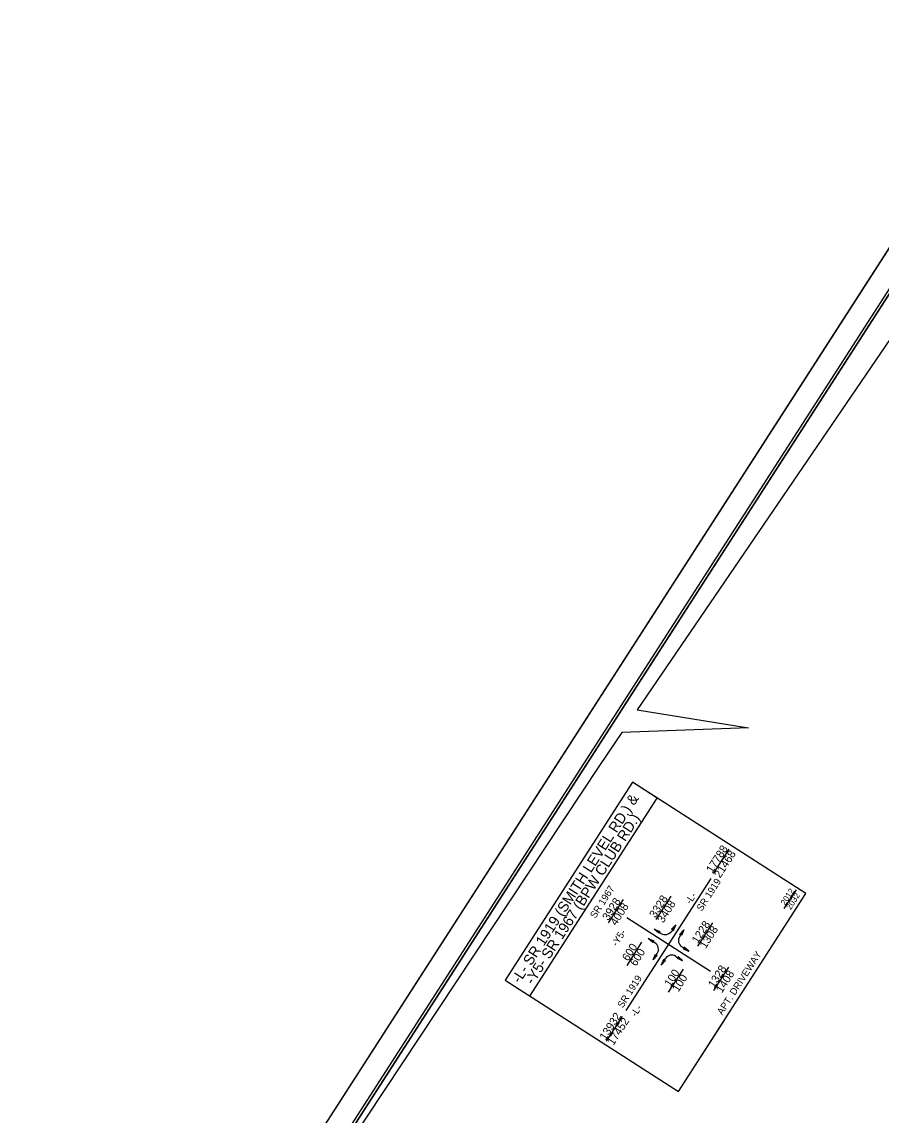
# Model space of a CAD drawing. Extents: x 1976127 to 1977958, y 779377 to 781490.
# Drawn here: x 1976127 to 1976899, y 780410 to 781394 of the extents above; entities that cross this region are included whole.
import ezdxf

# ---------------------------------------------------------------- set-up
doc = ezdxf.new("R2010")
doc.units = 0
for name, color, linetype in [('Prop PHM Label Text', 7, 'Continuous'), ('Prop PHM White Label Box', 7, 'Continuous'), ('Sheet Clip Boundary CELL', 7, 'Continuous'), ('Sheet Cutting Line CELL', 7, 'Continuous'), ('Sheet North Arrow CELL', 7, 'Continuous'), ('Sheet Plan CELL', 7, 'Continuous'), ('Sheet Plan Layout CELL', 7, 'Continuous'), ('Sheet Plot Border Inside CELL', 7, 'Continuous'), ('Sheet Plot Border Outside CELL', 7, 'Continuous')]:
    doc.layers.add(name, color=color, linetype=linetype)

msp = doc.modelspace()

# ---------------------------------------------------------------- linework, layer by layer
at = {"layer": 'Prop PHM Label Text'}
for p, q in [((1976697.94, 780695.58), (1976675.81, 780709.8)), ((1976583.34, 780517.38), (1976697.94, 780695.58)), ((1976748.46, 780627.55), (1976762.65, 780649.61)), ((1976670.04, 780504.29), (1976746.4, 780623.03)), ((1976812.25, 780596.14), (1976823.07, 780612.96)), ((1976654.2, 780583.36), (1976667.6, 780604.18)), ((1976697.01, 780586.39), (1976710.4, 780607.22)), ((1976745.81, 780539.49), (1976670.63, 780587.84)), ((1976714.61, 780581.53), (1976710.97, 780575.87)), ((1976734.43, 780562.33), (1976747.82, 780583.16)), ((1976695.85, 780565.3), (1976689.89, 780569.13)), ((1976701.29, 780573.77), (1976695.34, 780577.6)), ((1976721.82, 780576.89), (1976718.18, 780571.23)), ((1976670.8, 780544.91), (1976684.19, 780565.74)), ((1976720.28, 780561.56), (1976726.24, 780557.73)), ((1976694.31, 780549.97), (1976697.95, 780555.63)), ((1976701.52, 780545.32), (1976705.16, 780550.98)), ((1976714.84, 780553.09), (1976720.79, 780549.26)), ((1976708.21, 780520.85), (1976721.61, 780541.68)), ((1976748.92, 780522.45), (1976762.31, 780543.27)), ((1976652.43, 780476.69), (1976666.85, 780499.12))]:
    msp.add_line(p, q, dxfattribs=at)
for points in [[(1976712.47, 780576.49), (1976714.61, 780581.53), (1976710.86, 780577.48), (1976712.04, 780577.54)], [(1976693.93, 780565.43), (1976689.89, 780569.13), (1976694.98, 780567), (1976693.88, 780566.57)], [(1976699.38, 780573.9), (1976695.34, 780577.6), (1976700.43, 780575.47), (1976699.33, 780575.03)], [(1976718.12, 780572.85), (1976721.82, 780576.89), (1976719.69, 780571.8), (1976719.26, 780572.9)], [(1976721.19, 780559.87), (1976726.24, 780557.73), (1976722.19, 780561.47), (1976722.25, 780560.29)], [(1976698.01, 780554), (1976694.31, 780549.97), (1976696.44, 780555.05), (1976696.87, 780553.95)], [(1976703.66, 780550.37), (1976701.52, 780545.32), (1976705.27, 780549.37), (1976704.09, 780549.31)], [(1976715.75, 780551.4), (1976720.79, 780549.26), (1976716.75, 780553), (1976716.81, 780551.82)]]:
    msp.add_lwpolyline(points, close=True, dxfattribs=at)
for centre, start, end in [((1976705.08, 780579.66), 237.25497, 327.25497), ((1976724.07, 780567.44), 147.25497, 237.25497), ((1976692.06, 780559.41), 327.25497, 57.25497), ((1976711.05, 780547.2), 57.25497, 147.25497)]:
    msp.add_arc(centre, 7, start, end, dxfattribs=at)
at = {"layer": 'Prop PHM White Label Box'}
msp.add_lwpolyline([(1976717.11, 780431.36), (1976831.71, 780609.55), (1976675.81, 780709.8), (1976561.22, 780531.61)], close=True, dxfattribs=at)
at = {"layer": 'Sheet Clip Boundary CELL'}
msp.add_lwpolyline([(1977101.08, 779831.01), (1977215.67, 780009.21), (1977355.49, 779919.29), (1977890.17, 780737.44), (1977684.74, 780893.76), (1977248.3, 781047.23), (1977166.45, 781076.01), (1977126.79, 781101.54), (1977076.66, 781133.9), (1977065.02, 781118.14), (1976959.89, 781185.72), (1976680, 780774.86), (1976779.92, 780758.82), (1976666.09, 780754.45), (1976646.02, 780724.99), (1976307, 780212.91), (1976557.04, 780088.18), (1976950.5, 779704.75)], close=True, dxfattribs=at)
at = {"layer": 'Sheet Cutting Line CELL'}
msp.add_line((1977037.29, 781394.01), (1976126.68, 779978.04), dxfattribs=at)
at = {"layer": 'Sheet North Arrow CELL'}
msp.add_line((1976717.11, 780431.36), (1976758.45, 780495.65), dxfattribs=at)
at = {"layer": 'Sheet Plan CELL'}
for points in [[(1977047.02, 781367.57), (1976235.65, 780105.91), (1977118.79, 779537.96), (1977930.15, 780799.6)], [(1977118.79, 779537.96), (1976235.66, 780105.87), (1976938.79, 781199.29), (1977065.02, 781118.14), (1977173.23, 781286.38), (1977930.15, 780799.6)]]:
    msp.add_lwpolyline(points, close=True, dxfattribs=at)
at = {"layer": 'Sheet Plan Layout CELL'}
msp.add_lwpolyline([(1976235.66, 780105.87), (1977118.79, 779537.96), (1977930.14, 780799.59), (1977224.88, 781253.14), (1977095.47, 781051.91), (1976917.59, 781166.31)], close=True, dxfattribs=at)
at = {"layer": 'Sheet Plot Border Inside CELL'}
msp.add_lwpolyline([(1977037.88, 779407.5), (1977939.01, 780808.75), (1977051.68, 781379.41), (1976150.54, 779978.16)], close=True, dxfattribs=at)
at = {"layer": 'Sheet Plot Border Outside CELL'}
msp.add_lwpolyline([(1977047.67, 779385.75), (1977958.28, 780801.72), (1977037.29, 781394.01), (1976126.68, 779978.04)], close=True, dxfattribs=at)

# ---------------------------------------------------------------- texts
at = {"layer": 'Prop PHM Label Text'}
for s, height, p in [('-L- SR 1919 (SMITH LEVEL RD.) &', 9.414, (1976574.39, 780528.21)), ('-Y5- SR 1967 (BPW CLUB RD.)', 9.414, (1976586.25, 780526.95)), ('17788', 7.2, (1976747.44, 780627.58)), ('21468', 7.2, (1976754.55, 780623.01)), ('SR 1967', 6.276, (1976642.32, 780586.76)), ('SR 1919', 6.276, (1976738.05, 780593.15)), ('3328', 7.2, (1976696.27, 780587.14)), ('-L-', 6.276, (1976728.01, 780599.61)), ('2012', 5.4, (1976812.98, 780598.54)), ('2032', 5.4, (1976817.97, 780594.57)), ('3928', 7.2, (1976654, 780584.75)), ('4008', 7.2, (1976661.11, 780580.18)), ('3408', 7.2, (1976703.38, 780582.57)), ('1228', 7.2, (1976734.43, 780564.08)), ('1308', 7.2, (1976741.54, 780559.51)), ('-Y5-', 6.276, (1976661.66, 780561.54)), ('600', 7.2, (1976671.8, 780548.25)), ('600', 7.2, (1976678.9, 780543.68)), ('APT. DRIVEWAY', 6.276, (1976756.49, 780499.87)), ('100', 7.2, (1976709.78, 780525.04)), ('1328', 7.2, (1976749.04, 780524.16)), ('1408', 7.2, (1976756.15, 780519.59)), ('SR 1919', 6.276, (1976666.87, 780506.02)), ('100', 7.2, (1976716.89, 780520.47)), ('13932', 7.2, (1976651.5, 780477.06)), ('-L-', 6.276, (1976678.88, 780498.3)), ('17452', 7.2, (1976658.61, 780472.49))]:
    msp.add_text(s, height=height, rotation=57.2639, dxfattribs=at).set_placement(p)

doc.saveas('drawing.dxf')
